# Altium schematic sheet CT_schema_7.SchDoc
size 262 x 245 mm
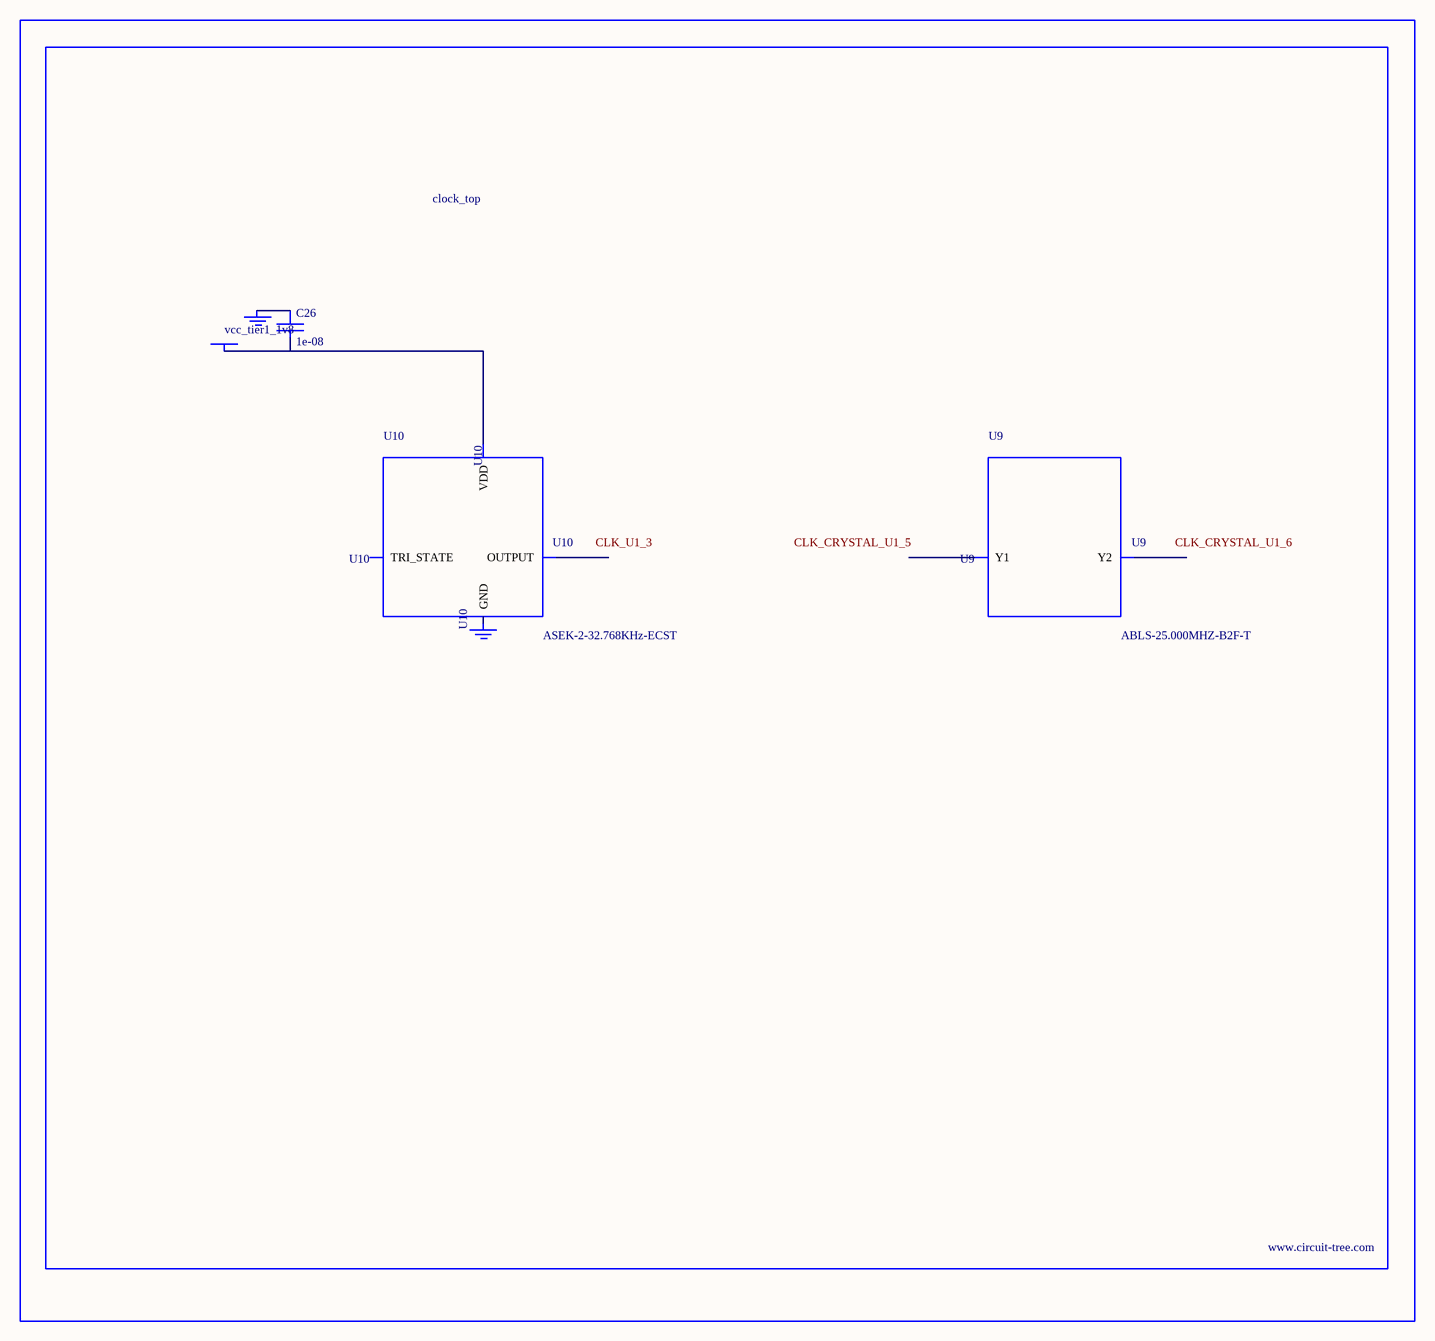
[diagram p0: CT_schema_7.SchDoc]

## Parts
BORDER6  (no value)
C26  1e-08  [C0402]
GND_INSTANCE_6_0  (no value)
GND_INSTANCE_6_1  (no value)
POWER_INSTANCE_6_0  vcc_tier1_1v8
U9  ABLS-25.000MHZ-B2F-T  [ABLS-25.000MHZ-B2F-T]
U10  ASEK-2-32.768KHz-ECST  [ASEK]

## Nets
NetC26_1: C26.1 GND_INSTANCE_6_0.0(GND)
NetC26_2: C26.2 POWER_INSTANCE_6_0.0(PWR) U10.4(VDD)

Not connected (* = marked no-connect by the designer): GND_INSTANCE_6_1 0(GND); U9 1(Y1) 2(Y2); U10 1(TRI_STATE) 2(GND) 3(OUTPUT)

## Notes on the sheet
- Labels drawn without touching a wire or pin: CLK_CRYSTAL_U1_5, CLK_CRYSTAL_U1_6, CLK_U1_3

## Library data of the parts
BORDER6 = BORDER_PAGE6
C26 = C0402C103K3RAC
GND_INSTANCE_6_0 GND_INSTANCE_6_1 = GND
POWER_INSTANCE_6_0 = PWR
